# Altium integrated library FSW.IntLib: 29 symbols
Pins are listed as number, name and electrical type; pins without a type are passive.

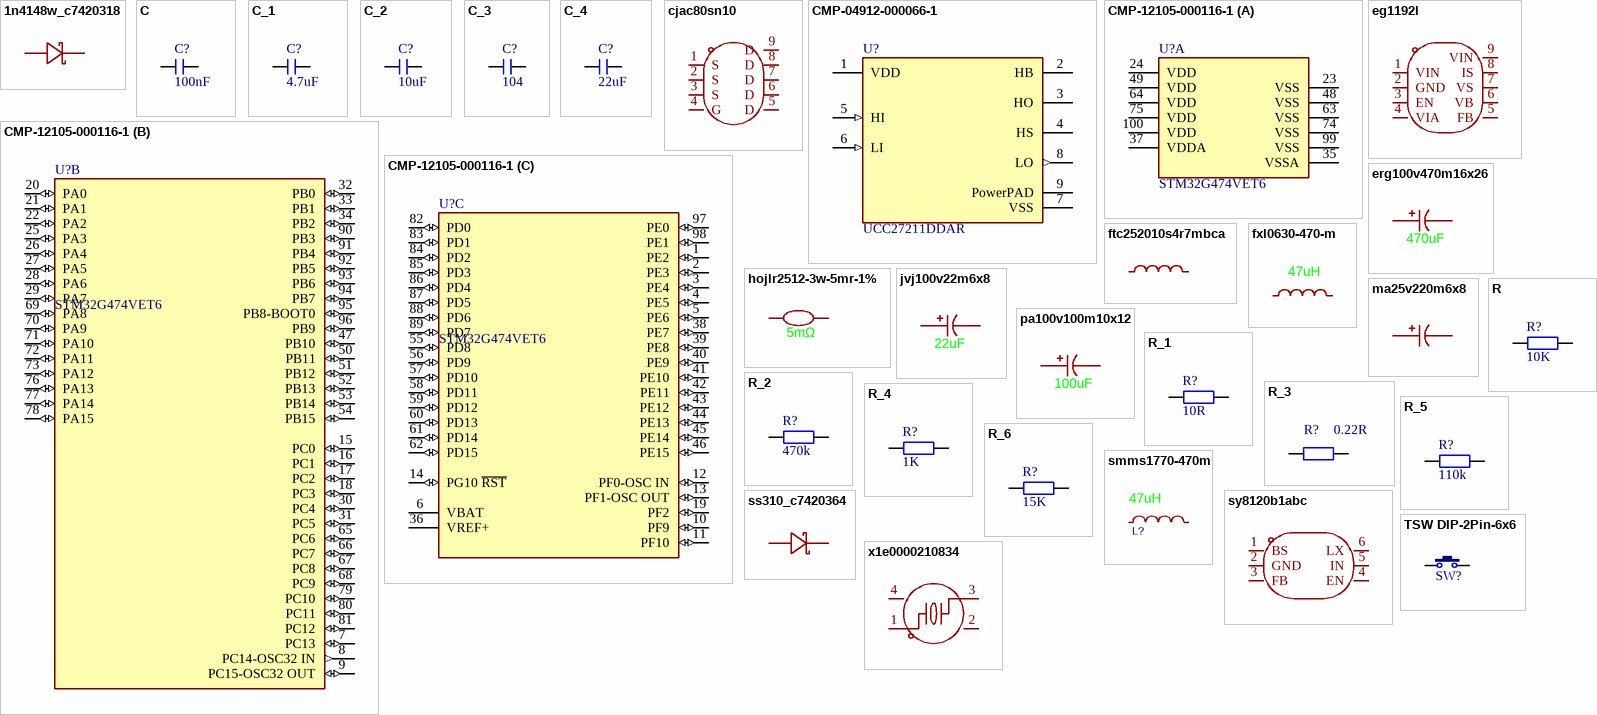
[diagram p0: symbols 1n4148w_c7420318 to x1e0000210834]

## 1n4148w_c7420318
designator D?  (value not drawn)
二极管配置:独立式;整流电流:150mA;直流反向耐压(Vr):100V;正向压降(Vf):1.25V@150mA;反向恢复时间(Trr):4ns;; Manufacturer: R+O(宏嘉诚); AddInBom: yes; ModelId: 5054d9b7be8b429dad093a54b517b4dd; ModelName: SOD-123_L2.7-W1.6-LS3.7-FD; ModelTransform: 145.669,61.024,0,0,0,0,0,0,0; Diode Configuration: 独立式; Pd - Power Dissipation: 400mW; Current - Rectified: 150mA; Voltage - DC Reverse(Vr): 100V; Non-Repetitive Peak Forward Surge Current: 2A; Reverse Leakage Current (Ir): 1uA@75V; Reverse Recovery Time (trr): 4ns; Operating Junction Temperature Range: -55℃~+150℃
footprint SOD-123_L2.7-W1.6-LS3.7-FD
pins: 1 A, 2 K

## C
designator C?, comment 100nF
无极性贴片电容; 版权归属: 源创客; 材质: X7R
footprint C 0201_L (无极性贴片电容)
footprint C 0402_L (无极性贴片电容)
footprint C 0603_L (无极性贴片电容)
footprint C 0805_L (无极性贴片电容)
footprint C 1206_L (无极性贴片电容)
footprint C 1210_L (无极性贴片电容)
footprint C 1808_L (无极性贴片电容)
footprint C 1812_L (无极性贴片电容)
footprint C 1825_L (无极性贴片电容)
footprint C 2225_L (无极性贴片电容)
footprint C 0201_M (无极性贴片电容)
footprint C 0402_M (无极性贴片电容)
footprint C 0603_M (无极性贴片电容)
footprint C 0805_M (无极性贴片电容)
footprint C 1206_M (无极性贴片电容)
footprint C 1210_M (无极性贴片电容)
footprint C 1808_M (无极性贴片电容)
footprint C 1812_M (无极性贴片电容)
footprint C 1825_M (无极性贴片电容)
footprint C 2225_M (无极性贴片电容)
pins: 1, 2

## C_1
designator C?, comment 4.7uF
无极性贴片电容; 版权归属: 源创客; 材质: X7R
footprint C 0201_L (无极性贴片电容)
footprint C 0402_L (无极性贴片电容)
footprint C 0603_L (无极性贴片电容)
footprint C 0805_L (无极性贴片电容)
footprint C 1206_L (无极性贴片电容)
footprint C 1210_L (无极性贴片电容)
footprint C 1808_L (无极性贴片电容)
footprint C 1812_L (无极性贴片电容)
footprint C 1825_L (无极性贴片电容)
footprint C 2225_L (无极性贴片电容)
footprint C 0201_M (无极性贴片电容)
footprint C 0402_M (无极性贴片电容)
footprint C 0603_M (无极性贴片电容)
footprint C 0805_M (无极性贴片电容)
footprint C 1206_M (无极性贴片电容)
footprint C 1210_M (无极性贴片电容)
footprint C 1808_M (无极性贴片电容)
footprint C 1812_M (无极性贴片电容)
footprint C 1825_M (无极性贴片电容)
footprint C 2225_M (无极性贴片电容)
pins: 1, 2

## C_2
designator C?, comment 10uF
无极性贴片电容; 版权归属: 源创客; 材质: X7R
footprint C 0201_L (无极性贴片电容)
footprint C 0402_L (无极性贴片电容)
footprint C 0603_L (无极性贴片电容)
footprint C 0805_L (无极性贴片电容)
footprint C 1206_L (无极性贴片电容)
footprint C 1210_L (无极性贴片电容)
footprint C 1808_L (无极性贴片电容)
footprint C 1812_L (无极性贴片电容)
footprint C 1825_L (无极性贴片电容)
footprint C 2225_L (无极性贴片电容)
footprint C 0201_M (无极性贴片电容)
footprint C 0402_M (无极性贴片电容)
footprint C 0603_M (无极性贴片电容)
footprint C 0805_M (无极性贴片电容)
footprint C 1206_M (无极性贴片电容)
footprint C 1210_M (无极性贴片电容)
footprint C 1808_M (无极性贴片电容)
footprint C 1812_M (无极性贴片电容)
footprint C 1825_M (无极性贴片电容)
footprint C 2225_M (无极性贴片电容)
pins: 1, 2

## C_3
designator C?, comment 104
无极性贴片电容; 版权归属: 源创客; 材质: X7R
footprint C 0201_L (无极性贴片电容)
footprint C 0402_L (无极性贴片电容)
footprint C 0603_L (无极性贴片电容)
footprint C 0805_L (无极性贴片电容)
footprint C 1206_L (无极性贴片电容)
footprint C 1210_L (无极性贴片电容)
footprint C 1808_L (无极性贴片电容)
footprint C 1812_L (无极性贴片电容)
footprint C 1825_L (无极性贴片电容)
footprint C 2225_L (无极性贴片电容)
footprint C 0201_M (无极性贴片电容)
footprint C 0402_M (无极性贴片电容)
footprint C 0603_M (无极性贴片电容)
footprint C 0805_M (无极性贴片电容)
footprint C 1206_M (无极性贴片电容)
footprint C 1210_M (无极性贴片电容)
footprint C 1808_M (无极性贴片电容)
footprint C 1812_M (无极性贴片电容)
footprint C 1825_M (无极性贴片电容)
footprint C 2225_M (无极性贴片电容)
pins: 1, 2

## C_4
designator C?, comment 22uF
无极性贴片电容; 版权归属: 源创客; 材质: X7R
footprint C 0201_L (无极性贴片电容)
footprint C 0402_L (无极性贴片电容)
footprint C 0603_L (无极性贴片电容)
footprint C 0805_L (无极性贴片电容)
footprint C 1206_L (无极性贴片电容)
footprint C 1210_L (无极性贴片电容)
footprint C 1808_L (无极性贴片电容)
footprint C 1812_L (无极性贴片电容)
footprint C 1825_L (无极性贴片电容)
footprint C 2225_L (无极性贴片电容)
footprint C 0201_M (无极性贴片电容)
footprint C 0402_M (无极性贴片电容)
footprint C 0603_M (无极性贴片电容)
footprint C 0805_M (无极性贴片电容)
footprint C 1206_M (无极性贴片电容)
footprint C 1210_M (无极性贴片电容)
footprint C 1808_M (无极性贴片电容)
footprint C 1812_M (无极性贴片电容)
footprint C 1825_M (无极性贴片电容)
footprint C 2225_M (无极性贴片电容)
pins: 1, 2

## cjac80sn10
designator Q?  (value not drawn)
数量:1个N沟道;漏源电压(Vdss):100V;连续漏极电流(Id):80A;导通电阻(RDS(on)):10.5mΩ@4.5V;耗散功率(Pd):100W;阈值电压(Vgs(th)):2.5V;; Manufacturer: CJ(江苏长电/长晶); AddInBom: yes; ModelId: 64dd0a0ad16f4146a485008a6fd3b168; ModelName: PDFN-8_L5.8-W5.0-P1.27-LS6.0-BL; ModelTransform: 193.7004,238.189,0,0,0,0,0,0,0; Number: 1个N沟道; Drain to Source Voltage: 100V; Current - Continuous Drain(Id): 80A; Pd - Power Dissipation: 100W; Gate Threshold Voltage (Vgs(th)): 2.5V; Gate Charge(Qg): 100nC@10V; Input Capacitance(Ciss): 3.15nF; Reverse Transfer Capacitance (Crss@Vds): 8pF; Type: N沟道; Output Capacitance(Coss): 650pF
footprint PDFN-8_L5.8-W5.0-P1.27-LS6.0-BL
pins: 1 S, 2 S, 3 S, 4 G, 5 D, 6 D, 7 D, 8 D, 9 D

## CMP-04912-000066-1
designator U?, comment UCC27211DDAR
IC GATE DRVR HALF-BRIDGE 8SOPWR; Supply Current: 4A; Number of Channels: 2; Turn-On Delay Time: 40ns; Max Output Current: 4.5A; Max Supply Voltage: 17V; Max Supply Current: 4.3mA; Fall Time: 400ns; Min Supply Voltage: 8V; Operating Supply Voltage: 12V; Rise Time: 600ns
footprint FP-DDA0008E-IPC_C
footprint FP-DDA0008E-IPC_A
footprint FP-DDA0008E-MFG
footprint FP-DDA0008E-IPC_B
pins: 1 VDD (power), 2 HB (power), 3 HO, 4 HS, 5 HI (in), 6 LI (in), 7 VSS (power), 8 LO (out), 9 PowerPAD (power)

## CMP-12105-000116-1
designator U?, comment STM32G474VET6
IC MCU 32BIT 512KB FLASH 100LQFP
footprint FP-LQFP100-1L-IPC_B
footprint FP-LQFP100-1L-IPC_A
footprint FP-LQFP100-1L-IPC_C
footprint FP-LQFP100-1L-MFG
part A pins: 23 VSS (power), 24 VDD (power), 35 VSSA (power), 37 VDDA (power), 48 VSS (power), 49 VDD (power), 63 VSS (power), 64 VDD (power), 74 VSS (power), 75 VDD (power), 99 VSS (power), 100 VDD (power)
part B pins: 7 PC13 (io), 8 PC14-OSC32 IN (out), 9 PC15-OSC32 OUT (io), 15 PC0 (io), 16 PC1 (io), 17 PC2 (io), 18 PC3 (io), 20 PA0 (io), 21 PA1 (io), 22 PA2 (io), 25 PA3 (io), 26 PA4 (io), 27 PA5 (io), 28 PA6 (io), 29 PA7 (io), 30 PC4 (io), 31 PC5 (io), 32 PB0 (io), 33 PB1 (io), 34 PB2 (io), 47 PB10 (io), 50 PB11 (io), 51 PB12 (io), 52 PB13 (io), 53 PB14 (io), 54 PB15 (io), 65 PC6 (io), 66 PC7 (io), 67 PC8 (io), 68 PC9 (io), 69 PA8 (io), 70 PA9 (io), 71 PA10 (io), 72 PA11 (io), 73 PA12 (io), 76 PA13 (io), 77 PA14 (io), 78 PA15 (io), 79 PC10 (io), 80 PC11 (io), 81 PC12 (io), 90 PB3 (io), 91 PB4 (io), 92 PB5 (io), 93 PB6 (io), 94 PB7 (io), 95 PB8-BOOT0 (io), 96 PB9 (io)
part C pins: 1 PE2 (io), 2 PE3 (io), 3 PE4 (io), 4 PE5 (io), 5 PE6 (io), 6 VBAT (power), 10 PF9 (io), 11 PF10 (io), 12 PF0-OSC IN (io), 13 PF1-OSC OUT (io), 14 PG10 ~{RST} (io), 19 PF2 (io), 36 VREF+ (power), 38 PE7 (io), 39 PE8 (io), 40 PE9 (io), 41 PE10 (io), 42 PE11 (io), 43 PE12 (io), 44 PE13 (io), 45 PE14 (io), 46 PE15 (io), 55 PD8 (io), 56 PD9 (io), 57 PD10 (io), 58 PD11 (io), 59 PD12 (io), 60 PD13 (io), 61 PD14 (io), 62 PD15 (io), 82 PD0 (io), 83 PD1 (io), 84 PD2 (io), 85 PD3 (io), 86 PD4 (io), 87 PD5 (io), 88 PD6 (io), 89 PD7 (io), 97 PE0 (io), 98 PE1 (io)

## eg1192l
designator U?  (value not drawn)
功能类型:降压型;工作电压:10V~100V;输出电压:-;输出电流:3A;输出类型:可调;; Manufacturer: EG(屹晶微); AddInBom: yes; ModelId: d3e00daa36c445139c055a3b9efb85d2; ModelName: ESOP-8_L4.9-W3.9-H1.6-LS6.0-P1.27; ModelTransform: 240.157,192.913,0,90,0,0,0,0,0; Function: 降压型; Output Current: 3A; Frequency - Switching: 110kHz; Synchronous Rectifier: 否; Number of Outputs: 1; Topology: 降压式; Quiescent Current: 2mA; Switch tube (built-in/external): 内置; Output Type: 可调
footprint ESOP-8_L4.9-W3.9-P1.27-LS6.0-BL-EP
pins: 1 VIN, 2 GND, 3 EN, 4 VIA, 5 FB, 6 VB, 7 VS, 8 IS, 9 VIN

## erg100v470m16x26
designator C?  value 470uF  (hidden comment: erg100v470m16x26)
容值:470uF;精度:±20%;额定电压:100V;纹波电流:1.62A@100kHz;等效串联电阻(ESR):45mΩ@100kHz;; Manufacturer: JIERR(捷而瑞); AddInBom: yes; ModelId: a842c2f395fb43008390029215713635; ModelName: CAP-TH_BD16.0-P7.5-D0.8-FD; ModelTransform: 629.92,629.92,0,0,0,0,0,0,-196.85; Tolerance: ±20%; Voltage Rating: 100V; Pin Spacing: 7.5mm; Lifetime: 2000hrs@105℃
footprint CAP-TH_BD16.0-P7.50-D0.8-FD
pins: 1, 2

## ftc252010s4r7mbca
designator L?  (value not drawn)
电感值:4.7uH;精度:±20%;额定电流:2A;饱和电流(Isat):2.6A;类型:-;; Manufacturer: cjiang(长江微电); AddInBom: yes; ModelId: e143e04106934774881cec608355723f; ModelName: IND-SMD_L2.5-W2.0-VLS252012CX-150M; ModelTransform: 98.504,78.819,0,0,0,0,-0.004,-0.003,0; Value: 4.7uH; Tolerance: ±20%; Current Rating: 2A; Current - Saturation(Isat): 2.6A; DC Resistance(DCR): 160mΩ
footprint IND-SMD_L2.5-W2.0-VLS252012CX-150M
pins: 1, 2

## fxl0630-470-m
designator L?  value 47uH  (hidden comment: fxl0630-470-m)
电感值:47uH;精度:±20%;额定电流:1.5A;饱和电流(Isat):2A;类型:一体成型电感;; Manufacturer: cjiang(长江微电); AddInBom: yes; ModelId: 6712504104d74f0ca01cd7d0df9965b7; ModelName: IND-SMD_L7.0-W6.6-H2.8_FXL0630; ModelTransform: 275.59,259.842,0,0,0,0,0,0,0; Tolerance: ±20%; Rated Current: 1.5A; Saturation Current (Isat): 2A; DC Resistance (DCR): 385mΩ; Type: 一体成型电感
footprint IND-SMD_L7.0-W6.6_FXL0630
pins: 1, 2

## hojlr2512-3w-5mr-1%
designator R?  value 5mΩ  (hidden comment: hojlr2512-3w-5mr-1%)
电阻类型:采样电阻;阻值:5mΩ;精度:±1%;功率:3W;安装方式:贴片;; Manufacturer: Milliohm(毫欧); AddInBom: yes; ModelId: 2a92684014bd46c593e4aa7ce823c350; ModelName: RES-SMD_L6.4-W3.2-1; ModelTransform: 251.968,125.984,0,0,0,0,0,0,0; Tolerance: ±1%; Power(Watts): 3W; Mounting Sytle: 贴片
footprint RES-SMD_L6.4-W3.2-1
pins: 1, 2

## jvj100v22m6x8
designator C?  value 22uF  (hidden comment: jvj100v22m6x8)
容值:22uF;精度:±20%;额定电压:100V;纹波电流:60mA@120Hz;; Manufacturer: JIERR(捷而瑞); AddInBom: yes; ModelId: ccbda52dceed4b139172c40f75c9da3f; ModelName: CAP-SMD_BD6.3-L6.6-W6.6-LS7.3-FD-H7.7; ModelTransform: 287.401,259.842,0,0,0,0,0,0,0; Tolerance: ±20%; Voltage Rating: 100V; Lifetime: 2000hrs@105℃
footprint CAP-SMD_BD6.3-L6.6-W6.6-LS7.3-FD-H7.7
pins: 1, 2

## ma25v220m6x8
designator C?  (value not drawn)
容值:220uF;精度:±20%;额定电压:25V;纹波电流:2.9A@100kHz;等效串联电阻(ESR):28mΩ@100kHz;类型:聚合物;; Manufacturer: JIERR(捷而瑞); AddInBom: yes; ModelId: 697a8c63e3274188b68c96045bc3ea1c; ModelName: CAP-SMD_BD6.3-L6.6-W6.6-LS7.3-FD; ModelTransform: 287.401,259.842,0,180,0,0,0.001,0.001,0; Value: 220uF; Tolerance: ±20%; Voltage Rating: 25V; Type: 聚合物; Lifetime: 2000hrs@105℃
footprint CAP-SMD_BD6.3-L6.6-W6.6-LS7.3-FD
pins: 1, 2

## pa100v100m10x12
designator C?  value 100uF  (hidden comment: pa100v100m10x12)
容值:100uF;精度:±20%;额定电压:100V;纹波电流:2.6A@100kHz;等效串联电阻(ESR):40mΩ@100kHz;类型:聚合物;; Manufacturer: JIERR(捷而瑞); AddInBom: yes; ModelId: 6de71f258d10432db69c5a71396d9b6a; ModelName: CAP-TH_BD10.0-P5.00-D0.6-FD_2; ModelTransform: 393.69921,393.73898,0,0,0,0,0,0,-196.85; Tolerance: ±20%; Voltage Rating: 100V; Type: 聚合物; Pin Spacing: 5mm; Lifetime: 2000hrs@105℃
footprint CAP-TH_BD10.0-P5.00-D0.6-FD_2
pins: 1, 2

## R
designator R?, comment 10K
贴片电阻; 版权归属: 源创客
footprint R 0201_L (1/20W贴片电阻)
footprint R 0402_L (1/16W贴片电阻)
footprint R 0603_L (1/10W贴片电阻)
footprint R 0805_L (1/8W贴片电阻)
footprint R 1206_L (1/4W贴片电阻)
footprint R 1210_L (1/3W贴片电阻)
footprint R 1812_L (1/2W贴片电阻)
footprint R 2010_L (3/4W贴片电阻)
footprint R 2512_L (1W贴片电阻)
footprint R 0201_M (1/20W贴片电阻)
footprint R 0402_M (1/16W贴片电阻)
footprint R 0603_M (1/10W贴片电阻)
footprint R 0805_M (1/8W贴片电阻)
footprint R 1206_M (1/4W贴片电阻)
footprint R 1210_M (1/3W贴片电阻)
footprint R 1812_M (1/2W贴片电阻)
footprint R 2010_M (3/4W贴片电阻)
footprint R 2512_M (1W贴片电阻)
pins: 1, 2

## R_1
designator R?, comment 10R
贴片电阻; 版权归属: 源创客
footprint R 0201_L (1/20W贴片电阻)
footprint R 0402_L (1/16W贴片电阻)
footprint R 0603_L (1/10W贴片电阻)
footprint R 0805_L (1/8W贴片电阻)
footprint R 1206_L (1/4W贴片电阻)
footprint R 1210_L (1/3W贴片电阻)
footprint R 1812_L (1/2W贴片电阻)
footprint R 2010_L (3/4W贴片电阻)
footprint R 2512_L (1W贴片电阻)
footprint R 0201_M (1/20W贴片电阻)
footprint R 0402_M (1/16W贴片电阻)
footprint R 0603_M (1/10W贴片电阻)
footprint R 0805_M (1/8W贴片电阻)
footprint R 1206_M (1/4W贴片电阻)
footprint R 1210_M (1/3W贴片电阻)
footprint R 1812_M (1/2W贴片电阻)
footprint R 2010_M (3/4W贴片电阻)
footprint R 2512_M (1W贴片电阻)
pins: 1, 2

## R_2
designator R?, comment 470k
贴片电阻; 版权归属: 源创客
footprint R 0201_L (1/20W贴片电阻)
footprint R 0402_L (1/16W贴片电阻)
footprint R 0603_L (1/10W贴片电阻)
footprint R 0805_L (1/8W贴片电阻)
footprint R 1206_L (1/4W贴片电阻)
footprint R 1210_L (1/3W贴片电阻)
footprint R 1812_L (1/2W贴片电阻)
footprint R 2010_L (3/4W贴片电阻)
footprint R 2512_L (1W贴片电阻)
footprint R 0201_M (1/20W贴片电阻)
footprint R 0402_M (1/16W贴片电阻)
footprint R 0603_M (1/10W贴片电阻)
footprint R 0805_M (1/8W贴片电阻)
footprint R 1206_M (1/4W贴片电阻)
footprint R 1210_M (1/3W贴片电阻)
footprint R 1812_M (1/2W贴片电阻)
footprint R 2010_M (3/4W贴片电阻)
footprint R 2512_M (1W贴片电阻)
pins: 1, 2

## R_3
designator R?, comment 0.22R
贴片电阻; 版权归属: 源创客
footprint R 0201_L (1/20W贴片电阻)
footprint R 0402_L (1/16W贴片电阻)
footprint R 0603_L (1/10W贴片电阻)
footprint R 0805_L (1/8W贴片电阻)
footprint R 1206_L (1/4W贴片电阻)
footprint R 1210_L (1/3W贴片电阻)
footprint R 1812_L (1/2W贴片电阻)
footprint R 2010_L (3/4W贴片电阻)
footprint R 2512_L (1W贴片电阻)
footprint R 0201_M (1/20W贴片电阻)
footprint R 0402_M (1/16W贴片电阻)
footprint R 0603_M (1/10W贴片电阻)
footprint R 0805_M (1/8W贴片电阻)
footprint R 1206_M (1/4W贴片电阻)
footprint R 1210_M (1/3W贴片电阻)
footprint R 1812_M (1/2W贴片电阻)
footprint R 2010_M (3/4W贴片电阻)
footprint R 2512_M (1W贴片电阻)
pins: 1, 2

## R_4
designator R?, comment 1K
贴片电阻; 版权归属: 源创客
footprint R 0201_L (1/20W贴片电阻)
footprint R 0402_L (1/16W贴片电阻)
footprint R 0603_L (1/10W贴片电阻)
footprint R 0805_L (1/8W贴片电阻)
footprint R 1206_L (1/4W贴片电阻)
footprint R 1210_L (1/3W贴片电阻)
footprint R 1812_L (1/2W贴片电阻)
footprint R 2010_L (3/4W贴片电阻)
footprint R 2512_L (1W贴片电阻)
footprint R 0201_M (1/20W贴片电阻)
footprint R 0402_M (1/16W贴片电阻)
footprint R 0603_M (1/10W贴片电阻)
footprint R 0805_M (1/8W贴片电阻)
footprint R 1206_M (1/4W贴片电阻)
footprint R 1210_M (1/3W贴片电阻)
footprint R 1812_M (1/2W贴片电阻)
footprint R 2010_M (3/4W贴片电阻)
footprint R 2512_M (1W贴片电阻)
pins: 1, 2

## R_5
designator R?, comment 110k
贴片电阻; 版权归属: 源创客
footprint R 0201_L (1/20W贴片电阻)
footprint R 0402_L (1/16W贴片电阻)
footprint R 0603_L (1/10W贴片电阻)
footprint R 0805_L (1/8W贴片电阻)
footprint R 1206_L (1/4W贴片电阻)
footprint R 1210_L (1/3W贴片电阻)
footprint R 1812_L (1/2W贴片电阻)
footprint R 2010_L (3/4W贴片电阻)
footprint R 2512_L (1W贴片电阻)
footprint R 0201_M (1/20W贴片电阻)
footprint R 0402_M (1/16W贴片电阻)
footprint R 0603_M (1/10W贴片电阻)
footprint R 0805_M (1/8W贴片电阻)
footprint R 1206_M (1/4W贴片电阻)
footprint R 1210_M (1/3W贴片电阻)
footprint R 1812_M (1/2W贴片电阻)
footprint R 2010_M (3/4W贴片电阻)
footprint R 2512_M (1W贴片电阻)
pins: 1, 2

## R_6
designator R?, comment 15K
贴片电阻; 版权归属: 源创客
footprint R 0201_L (1/20W贴片电阻)
footprint R 0402_L (1/16W贴片电阻)
footprint R 0603_L (1/10W贴片电阻)
footprint R 0805_L (1/8W贴片电阻)
footprint R 1206_L (1/4W贴片电阻)
footprint R 1210_L (1/3W贴片电阻)
footprint R 1812_L (1/2W贴片电阻)
footprint R 2010_L (3/4W贴片电阻)
footprint R 2512_L (1W贴片电阻)
footprint R 0201_M (1/20W贴片电阻)
footprint R 0402_M (1/16W贴片电阻)
footprint R 0603_M (1/10W贴片电阻)
footprint R 0805_M (1/8W贴片电阻)
footprint R 1206_M (1/4W贴片电阻)
footprint R 1210_M (1/3W贴片电阻)
footprint R 1812_M (1/2W贴片电阻)
footprint R 2010_M (3/4W贴片电阻)
footprint R 2512_M (1W贴片电阻)
pins: 1, 2

## smms1770-470m
designator L?  value 47uH  (hidden comment: smms1770-470m)
电感值:47uH;精度:±20%;额定电流:8.7A;饱和电流(Isat):16A;类型:一体成型电感;; Manufacturer: SXN(顺翔诺); AddInBom: yes; ModelId: d1dffc4284db41038928bca88ac39480; ModelName: IND-SMD_L17.5-W17.2-H7.0; ModelTransform: 688.975,675.19948,0,0,0,0,0,0,0; Tolerance: ±20%; Rated Current: 8.7A; Saturation Current (Isat): 16A; DC Resistance (DCR): 55mΩ; Type: 一体成型电感
footprint IND-SMD_L17.5-W17.2
pins: 1, 2

## ss310_c7420364
designator D?  (value not drawn)
二极管配置:独立式;正向压降(Vf):850mV@3A;直流反向耐压(Vr):100V;整流电流:3A;; Manufacturer: R+O(宏嘉诚); ManufacturerPart: SS310; AddInBom: yes; ModelId: 7e24bebe6cd74171ae8c9de6fc5b78aa; ModelName: SMA_L4.3-W2.6-LS5.0-FD; ModelTransform: 198.4248,103.5431,0,180,0,0,-0.001,0,0; Diode Configuration: 独立式; Voltage - DC Reverse(Vr): 100V; Current - Rectified: 3A; Reverse Leakage Current (Ir): 50uA@100V; Operating Junction Temperature Range: -55℃~+150℃; Non-Repetitive Peak Forward Surge Current: 80A
footprint SMA_L4.3-W2.6-LS5.0-FD
pins: 1 A, 2 K

## sy8120b1abc
designator U?  (value not drawn)
功能类型:降压型;工作电压:4.5V~18V;输出电压:-;输出电流:2A;输出类型:可调;; Manufacturer: Silergy(矽力杰); AddInBom: yes; ModelId: 18da8f6c14a34920b3e136b5c401a119; ModelName: SOT-23-6_L2.9-W1.6-H1.5-LS2.8-P0.95; ModelTransform: 110.236,113.364,0,90,0,0,0.0005,0.0005,0; Function: 降压型; Output Current: 2A; Frequency - Switching: 500kHz; Synchronous Rectifier: 是; Number of Outputs: 1; Topology: 降压式; Quiescent Current: 400uA; Switch tube (built-in/external): 内置; Output Type: 可调
footprint SOT-23-6_L2.9-W1.6-P0.95-LS2.8-BL
pins: 1 BS, 2 GND, 3 FB, 4 EN, 5 IN, 6 LX

## TSW DIP-2Pin-6x6
designator SW?, comment 6x6x5  (value not drawn)
2脚直插6x6轻触开关; BOM名称: 2脚轻触开关; 版权归属: 源创客
footprint TSW DIP-2Pin-6*6*6 (2Pin，6*6*6mm)
footprint TSW DIP-2Pin-6*6*4.3 (2Pin，6*6*4.3mm)
footprint TSW DIP-2Pin-6*6*9 (2Pin，6*6*9mm)
footprint TSW DIP-2Pin-6*6*5 (2Pin，6*6*5mm)
footprint TSW DIP-2Pin-6*6*7 (2Pin，6*6*7mm)
footprint TSW DIP-2Pin-6*6*8 (2Pin，6*6*8mm)
footprint TSW DIP-2Pin-6*6*10 (2Pin，6*6*10mm)
footprint TSW DIP-2Pin-6*6*11 (2Pin，6*6*11mm)
footprint TSW DIP-2Pin-6*6*12 (2Pin，6*6*12mm)
footprint TSW DIP-2Pin-6*6*13 (2Pin，6*6*13mm)
footprint TSW DIP-2Pin-6*6*14 (2Pin，6*6*14mm)
footprint TSW DIP-2Pin-6*6*15 (2Pin，6*6*15mm)
pins: 1, 2

## x1e0000210834
designator X?  (value not drawn)
晶振类型:贴片晶振;频率:48MHz;常温频差:±10ppm;负载电容:10pF;频率稳定度:±10ppm;; Manufacturer: EPSON(爱普生); AddInBom: yes; ModelId: ff2dfd5650294453a14147960efe1838; ModelName: CRYSTAL-SMD_4P-L3.2-W2.5-BL; ModelTransform: 125.984,98.425,0,0,0,0,0,0,0; Value: 48MHz; Normal temperature Frequency Tolerance: ±10ppm; Load Capacitance: 10pF; Equivalent Series Resistance(ESR): 40Ω
footprint CRYSTAL-SMD_4P-L3.2-W2.5-BL
pins: 1, 2 GND, 3, 4 GND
